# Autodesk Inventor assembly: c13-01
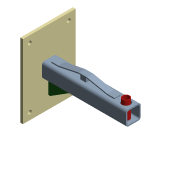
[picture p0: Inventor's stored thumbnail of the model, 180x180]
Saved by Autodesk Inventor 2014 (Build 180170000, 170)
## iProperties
Created: 2011-01
Part Number: c13-01
Document SubType Name: Assembly
Designer: Thom Tremblay
_SolveAssemblyDoc: Frame Generator Solve Assembly
_Version: 15.0.0
Author: Thom Tremblay
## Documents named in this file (5)
- C:\Inventor 2014 Essentials\Assemblies\Chapter 13\c13-01.iam
- C:\Inventor 2014 Essentials\Parts\Chapter 13\c13-01.ipt
- C:\Inventor 2014 Essentials\Parts\Chapter 13\c13-02.ipt
- C:\Inventor 2014 Essentials\Assemblies\Chapter 13\Frame\Frame c13-01.iam
- C:\Inventor 2014 Essentials\Parts\Chapter 13\c13-03.ipt
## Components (4 placed, 4 different names)
1. c13-01:1 — Mate:2
2. c13-02:1 — Flush:1
3. Frame c13-01:1 [sub-assembly] — Mate:3
4. c13-03:1 — Mate:1, Mate:2, Mate:3
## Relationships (4: Mate 3, Flush 1)
- Flush:1: c13-02:1
- Mate:1: c13-03:1
- Mate:2: c13-01:1 ↔ c13-03:1
- Mate:3: Frame c13-01:1 ↔ c13-03:1
